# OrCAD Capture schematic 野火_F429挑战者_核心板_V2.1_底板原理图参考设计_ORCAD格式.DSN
size A4; title: 野火_F429挑战者_核心板; rev: V2.1; note: B2B IO
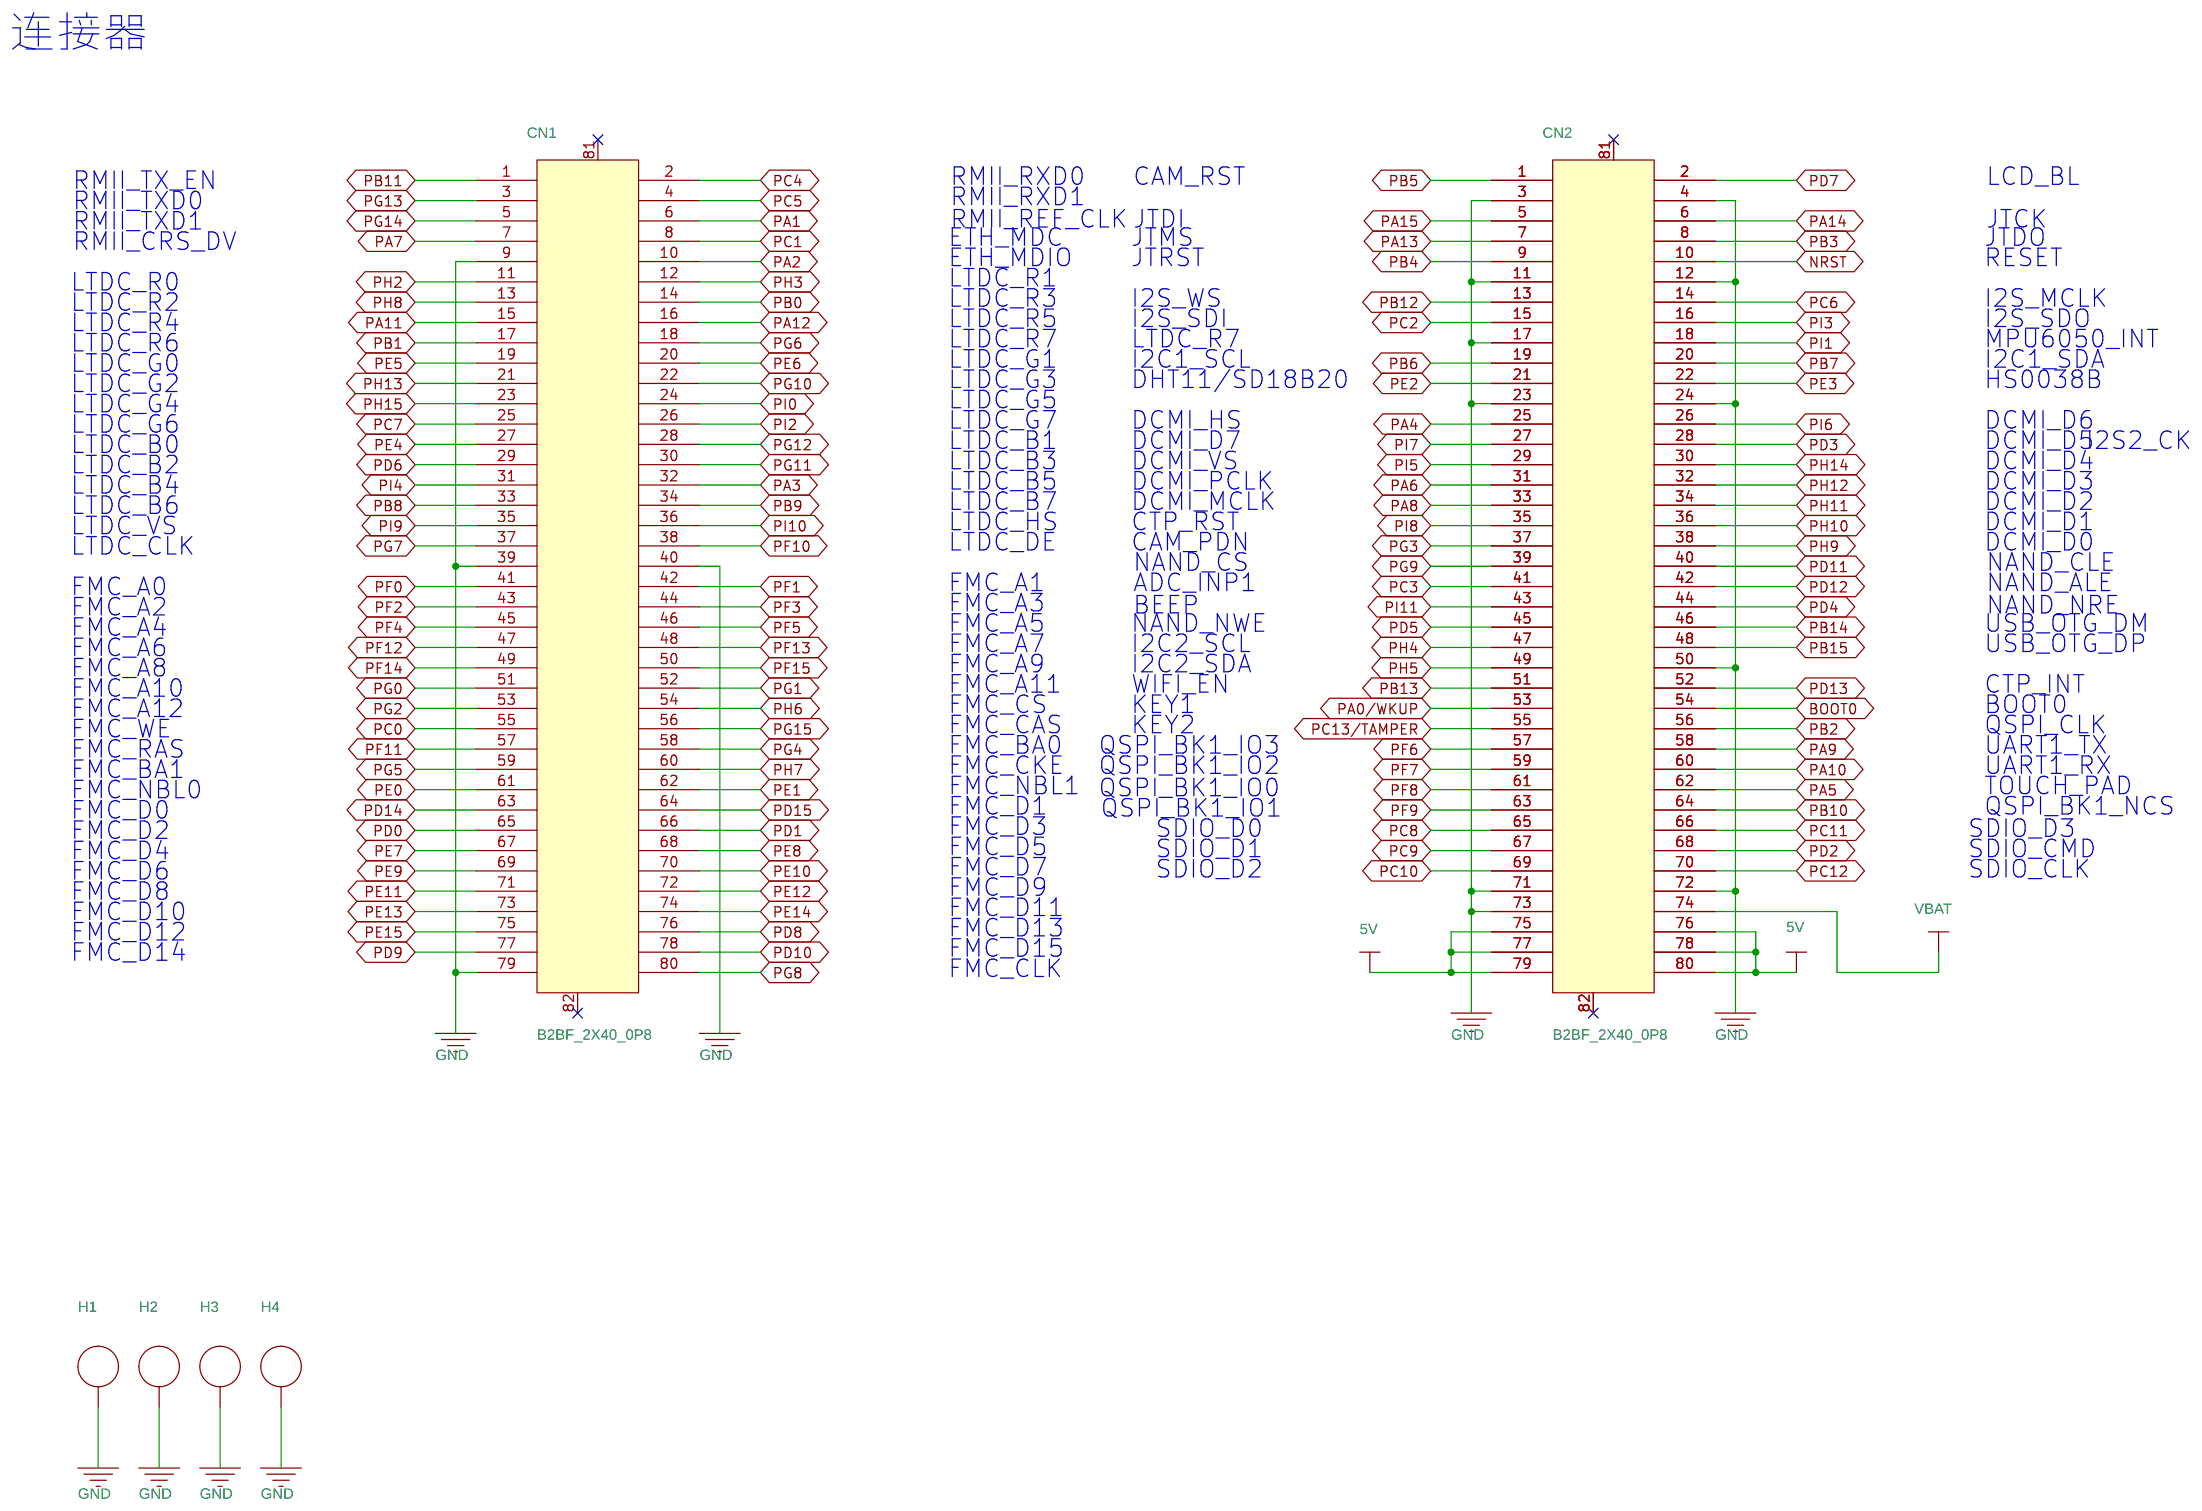
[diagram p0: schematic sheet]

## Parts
CN1  B2BF_2X40_0P8  [B2BF-2X40-0P8]
CN2  B2BF_2X40_0P8  [B2BF-2X40-0P8]
H1  3.0mm  [T3]
H2  3.0mm  [T3]
H3  3.0mm  [T3]
H4  3.0mm  [T3]

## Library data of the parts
CN1 CN2 = B2BF_2X40_0
H1-H4 = SPACER_0: FASTENER, STANDOFF 4.5MMX3.53XM3.0X0.5 ROUND THR .635"L BRASS; AGILE_PN: 280-76498; ASSY_OPT: DNP; CAD_APPROVED: Yes; HEIGHT: 16.13MM; MFG_NAME01: UNICORP; MFG_PN01: MSS251-R-1-A-16; ROHS: Yes

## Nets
5V: CN2.75 CN2.76 CN2.77 CN2.78 CN2.79 CN2.80
GND: CN1.9 CN1.39 CN1.40 CN1.79 CN2.3 CN2.4 CN2.11 CN2.12 CN2.17 CN2.23 CN2.24 CN2.50 CN2.71 CN2.72 CN2.73 H1.1(NC) H2.1(NC) H3.1(NC) H4.1(NC)
VBAT: CN2.74
BOOT0: CN2.54
NRST: CN2.10
PA0/WKUP: CN2.53
PA1: CN1.6
PA2: CN1.10
PA3: CN1.32
PA4: CN2.25
PA5: CN2.62
PA6: CN2.31
PA7: CN1.7
PA8: CN2.33
PA9: CN2.58
PA10: CN2.60
PA11: CN1.15
PA12: CN1.16
PA13: CN2.7
PA14: CN2.6
PA15: CN2.5
PB0: CN1.14
PB1: CN1.17
PB2: CN2.56
PB3: CN2.8
PB4: CN2.9
PB5: CN2.1
PB6: CN2.19
PB7: CN2.20
PB8: CN1.33
PB9: CN1.34
PB10: CN2.64
PB11: CN1.1
PB12: CN2.13
PB13: CN2.51
PB14: CN2.46
PB15: CN2.48
PC0: CN1.55
PC1: CN1.8
PC2: CN2.15
PC3: CN2.41
PC4: CN1.2
PC5: CN1.4
PC6: CN2.14
PC7: CN1.25
PC8: CN2.65
PC9: CN2.67
PC10: CN2.69
PC11: CN2.66
PC12: CN2.70
PC13/TAMPER: CN2.55
PD0: CN1.65
PD1: CN1.66
PD2: CN2.68
PD3: CN2.28
PD4: CN2.44
PD5: CN2.45
PD6: CN1.29
PD7: CN2.2
PD8: CN1.76
PD9: CN1.77
PD10: CN1.78
PD11: CN2.40
PD12: CN2.42
PD13: CN2.52
PD14: CN1.63
PD15: CN1.64
PE0: CN1.61
PE1: CN1.62
PE2: CN2.21
PE3: CN2.22
PE4: CN1.27
PE5: CN1.19
PE6: CN1.20
PE7: CN1.67
PE8: CN1.68
PE9: CN1.69
PE10: CN1.70
PE11: CN1.71
PE12: CN1.72
PE13: CN1.73
PE14: CN1.74
PE15: CN1.75
PF0: CN1.41
PF1: CN1.42
PF2: CN1.43
PF3: CN1.44
PF4: CN1.45
PF5: CN1.46
PF6: CN2.57
PF7: CN2.59
PF8: CN2.61
PF9: CN2.63
PF10: CN1.38
PF11: CN1.57
PF12: CN1.47
PF13: CN1.48
PF14: CN1.49
PF15: CN1.50
PG0: CN1.51
PG1: CN1.52
PG2: CN1.53
PG3: CN2.37
PG4: CN1.58
PG5: CN1.59
PG6: CN1.18
PG7: CN1.37
PG8: CN1.80
PG9: CN2.39
PG10: CN1.22
PG11: CN1.30
PG12: CN1.28
PG13: CN1.3
PG14: CN1.5
PG15: CN1.56
PH2: CN1.11
PH3: CN1.12
PH4: CN2.47
PH5: CN2.49
PH6: CN1.54
PH7: CN1.60
PH8: CN1.13
PH9: CN2.38
PH10: CN2.36
PH11: CN2.34
PH12: CN2.32
PH13: CN1.21
PH14: CN2.30
PH15: CN1.23
PI0: CN1.24
PI1: CN2.18
PI2: CN1.26
PI3: CN2.16
PI4: CN1.31
PI5: CN2.29
PI6: CN2.26
PI7: CN2.27
PI8: CN2.35
PI9: CN1.35
PI10: CN1.36
PI11: CN2.43

Not connected (* = marked no-connect by the designer): CN1 81* 82*; CN2 81* 82*

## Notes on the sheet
- 连接器
- RMII_RXD0
- CAM_RST
- LCD_BL
- RMII_TXD0
- RMII_TX_EN
- RMII_RXD1
- RMII_TXD1
- RMII_REF_CLK
- JTDI
- JTCK
- RMII_CRS_DV
- ETH_MDC
- JTMS
- JTDO
- ETH_MDIO
- JTRST
- RESET
- LTDC_R0
- LTDC_R1
- LTDC_R3
- I2S_WS
- I2S_MCLK
- LTDC_R2
- LTDC_R4
- LTDC_R5
- I2S_SDI
- I2S_SDO
- LTDC_R6
- LTDC_R7
- LTDC_R7
- MPU6050_INT
- LTDC_G0
- LTDC_G1
- I2C1_SCL
- I2C1_SDA
- LTDC_G2
- LTDC_G3
- DHT11/SD18B20
- HS0038B
- LTDC_G4
- LTDC_G5
- LTDC_G6
- LTDC_B1
- LTDC_G7
- DCMI_D7
- DCMI_HS
- DCMI_D5
- DCMI_D6
- I2S2_CK
- LTDC_B0
- LTDC_B2
- LTDC_B3
- DCMI_VS
- DCMI_D4
- LTDC_B4
- LTDC_B5
- DCMI_PCLK
- DCMI_D3
- LTDC_B6
- LTDC_B7
- DCMI_MCLK
- DCMI_D2
- LTDC_VS
- LTDC_HS
- CTP_RST
- DCMI_D1
- LTDC_CLK
- LTDC_DE
- CAM_PDN
- NAND_CS
- DCMI_D0
- NAND_CLE
- FMC_A0
- FMC_A1
- ADC_INP1
- NAND_ALE
- FMC_A2
- FMC_A3
- BEEP
- NAND_NRE
- FMC_A4
- FMC_A5
- NAND_NWE
- USB_OTG_DM
- FMC_A6
- FMC_A7
- I2C2_SCL
- USB_OTG_DP
- FMC_A8
- FMC_A9
- I2C2_SDA
- FMC_A10
- FMC_A11
- FMC_CS
- KEY1
- WIFI_EN
- BOOT0
- CTP_INT
- FMC_A12
- FMC_WE
- FMC_CAS
- KEY2
- QSPI_CLK
- FMC_RAS
- FMC_BA0
- QSPI_BK1_IO3
- UART1_TX
- FMC_BA1
- FMC_CKE
- QSPI_BK1_IO2
- UART1_RX
- FMC_NBL0
- FMC_NBL1
- QSPI_BK1_IO0
- TOUCH_PAD
- FMC_D0
- FMC_D1
- FMC_D3
- QSPI_BK1_IO1
- QSPI_BK1_NCS
- FMC_D2
- FMC_D4
- FMC_D5
- SDIO_D0
- SDIO_D1
- SDIO_CMD
- SDIO_D3
- FMC_D6
- FMC_D7
- SDIO_D2
- SDIO_CLK
- FMC_D8
- FMC_D9
- FMC_D10
- FMC_D11
- FMC_D12
- FMC_D13
- FMC_D14
- FMC_CLK
- FMC_D15
